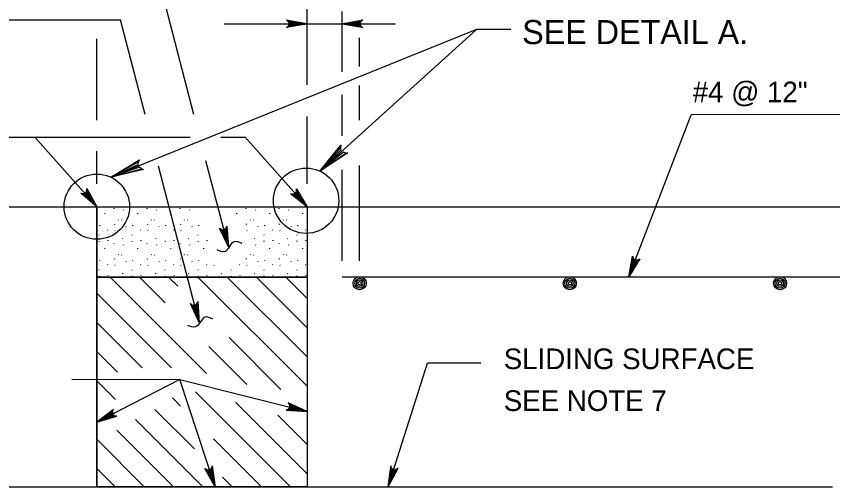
# Model space of a CAD drawing. Extents: x 2084213 to 2099800, y 976677 to 981262.
# Drawn here: x 2094864.1 to 2095252.4, y 979206.7 to 979430.6 of the extents above; entities that cross this region are included whole.
import ezdxf

# ---------------------------------------------------------------- set-up
doc = ezdxf.new("R2010")
doc.units = 0
for name, color, linetype in [('1', 7, 'Continuous'), ('2', 7, 'Continuous'), ('3', 7, 'Continuous')]:
    doc.layers.add(name, color=color, linetype=linetype)

msp = doc.modelspace()

# ---------------------------------------------------------------- linework, layer by layer
at = {"layer": '1'}
for p, q in [((2095002.37, 979398), (2095002.37, 979545.46)), ((2094948.57, 979383.86), (2094918.79, 979498.42)), ((2095019.04, 979404.17), (2095019.04, 979432.84)), ((2094732.6, 979428.91), (2094913.65, 979428.91)), ((2094925.34, 979383.93), (2094913.65, 979428.91)), ((2094962.99, 979427.06), (2095044.28, 979427.06)), ((2094902.37, 979381.16), (2094902.37, 979419.94)), ((2095027.37, 979406.69), (2095027.37, 979420.43)), ((2095027.37, 979381.14), (2095027.37, 979397.72)), ((2095019.04, 979373.78), (2095019.04, 979393.23)), ((2095155.38, 979306.66), (2095185.07, 979383.79)), ((2095259, 979383.92), (2095185.07, 979383.79)), ((2095002.37, 979350.87), (2095002.37, 979382.86)), ((2094794.55, 979373.09), (2094946.76, 979373.09)), ((2094902.37, 979339.99), (2094872.9, 979373.09)), ((2094961.33, 979373.09), (2094972.9, 979373.09)), ((2095002.37, 979339.99), (2094972.9, 979373.09)), ((2094902.37, 979350.87), (2094902.37, 979366.44)), ((2094964.96, 979320.8), (2094954.28, 979361.88)), ((2094951.1, 979284.85), (2094931.73, 979359.34)), ((2095019.04, 979314.25), (2095019.04, 979357.59)), ((2095027.37, 979314.25), (2095027.37, 979359.55)), ((2094435.37, 979339.99), (2094902.37, 979339.99)), ((2094902.37, 979339.99), (2095499.4, 979339.99)), ((2094902.37, 979339.99), (2094902.37, 979206.66)), ((2094906.14, 979336.57), (2094906.26, 979336.84)), ((2094910.47, 979339.26), (2094910.5, 979338.99)), ((2094915.1, 979338.47), (2094915.22, 979338.3)), ((2094921.84, 979336.57), (2094921.95, 979336.84)), ((2094926.16, 979339.26), (2094926.19, 979338.99)), ((2094930.79, 979338.47), (2094930.91, 979338.3)), ((2094937.53, 979336.57), (2094937.65, 979336.84)), ((2094941.86, 979339.26), (2094941.89, 979338.99)), ((2094946.48, 979338.47), (2094946.6, 979338.3)), ((2094968.91, 979336.57), (2094969.03, 979336.84)), ((2094973.24, 979339.26), (2094973.27, 979338.99)), ((2094977.87, 979338.47), (2094977.98, 979338.3)), ((2094984.61, 979336.57), (2094984.72, 979336.84)), ((2094988.93, 979339.26), (2094988.96, 979338.99)), ((2094993.56, 979338.47), (2094993.68, 979338.3)), ((2095000.3, 979336.57), (2095000.42, 979336.84)), ((2095002.37, 979339.99), (2095002.37, 979206.66)), ((2094912.49, 979333.76), (2094912.6, 979333.58)), ((2094914.17, 979333.69), (2094914.28, 979333.51)), ((2094928.18, 979333.76), (2094928.3, 979333.58)), ((2094929.86, 979333.69), (2094929.98, 979333.51)), ((2094943.87, 979333.76), (2094943.99, 979333.58)), ((2094945.55, 979333.69), (2094945.67, 979333.51)), ((2094975.26, 979333.76), (2094975.37, 979333.58)), ((2094976.94, 979333.69), (2094977.05, 979333.51)), ((2094990.95, 979333.76), (2094991.07, 979333.58)), ((2094992.63, 979333.69), (2094992.75, 979333.51)), ((2094903.75, 979330.89), (2094903.87, 979331.16)), ((2094907.44, 979329), (2094907.56, 979328.83)), ((2094910.75, 979331.57), (2094910.86, 979331.84)), ((2094910.93, 979328.68), (2094911.05, 979328.51)), ((2094916.14, 979330.55), (2094916.26, 979330.37)), ((2094919.45, 979330.89), (2094919.56, 979331.16)), ((2094923.13, 979329), (2094923.25, 979328.83)), ((2094926.44, 979331.57), (2094926.56, 979331.84)), ((2094926.62, 979328.68), (2094926.74, 979328.51)), ((2094931.84, 979330.55), (2094931.95, 979330.37)), ((2094935.14, 979330.89), (2094935.26, 979331.16)), ((2094938.83, 979329), (2094938.94, 979328.83)), ((2094942.13, 979331.57), (2094942.25, 979331.84)), ((2094942.31, 979328.68), (2094942.43, 979328.51)), ((2094947.53, 979330.55), (2094947.65, 979330.37)), ((2094950.83, 979330.89), (2094950.95, 979331.16)), ((2094973.51, 979331.57), (2094973.63, 979331.84)), ((2094973.7, 979328.68), (2094973.81, 979328.51)), ((2094978.91, 979330.55), (2094979.03, 979330.37)), ((2094982.22, 979330.89), (2094982.33, 979331.16)), ((2094985.9, 979329), (2094986.02, 979328.83)), ((2094989.21, 979331.57), (2094989.32, 979331.84)), ((2094989.39, 979328.68), (2094989.51, 979328.51)), ((2094994.61, 979330.55), (2094994.72, 979330.37)), ((2094997.91, 979330.89), (2094998.03, 979331.16)), ((2095001.6, 979329), (2095001.71, 979328.83)), ((2094903.36, 979326.59), (2094903.48, 979326.41)), ((2094914.67, 979324.61), (2094914.79, 979324.87)), ((2094919.05, 979326.59), (2094919.17, 979326.41)), ((2094930.36, 979324.61), (2094930.48, 979324.87)), ((2094946.05, 979324.61), (2094946.17, 979324.87)), ((2094950.44, 979326.59), (2094950.56, 979326.41)), ((2094977.44, 979324.61), (2094977.55, 979324.87)), ((2094981.82, 979326.59), (2094981.94, 979326.41)), ((2094993.13, 979324.61), (2094993.25, 979324.87)), ((2094997.52, 979326.59), (2094997.63, 979326.41)), ((2094903.46, 979323.4), (2094903.58, 979323.66)), ((2094907.55, 979323.97), (2094907.67, 979323.79)), ((2094910.47, 979322.66), (2094910.5, 979322.39)), ((2094915.1, 979321.88), (2094915.22, 979321.7)), ((2094919.15, 979323.4), (2094919.27, 979323.66)), ((2094923.24, 979323.97), (2094923.36, 979323.79)), ((2094926.16, 979322.66), (2094926.19, 979322.39)), ((2094930.79, 979321.88), (2094930.91, 979321.7)), ((2094934.84, 979323.4), (2094934.96, 979323.66)), ((2094938.94, 979323.97), (2094939.05, 979323.79)), ((2094941.86, 979322.66), (2094941.89, 979322.39)), ((2094946.48, 979321.88), (2094946.6, 979321.7)), ((2094950.54, 979323.4), (2094950.65, 979323.66)), ((2094954.63, 979323.97), (2094954.75, 979323.79)), ((2094977.87, 979321.88), (2094977.98, 979321.7)), ((2094981.92, 979323.4), (2094982.04, 979323.66)), ((2094986.01, 979323.97), (2094986.13, 979323.79)), ((2094988.93, 979322.66), (2094988.96, 979322.39)), ((2094993.56, 979321.88), (2094993.68, 979321.7)), ((2094997.61, 979323.4), (2094997.73, 979323.66)), ((2095001.71, 979323.97), (2095001.82, 979323.79)), ((2094906.14, 979319.98), (2094906.26, 979320.24)), ((2094912.49, 979317.16), (2094912.6, 979316.98)), ((2094914.17, 979317.09), (2094914.28, 979316.92)), ((2094921.84, 979319.98), (2094921.95, 979320.24)), ((2094928.18, 979317.16), (2094928.3, 979316.98)), ((2094929.86, 979317.09), (2094929.98, 979316.92)), ((2094937.53, 979319.98), (2094937.65, 979320.24)), ((2094943.87, 979317.16), (2094943.99, 979316.98)), ((2094945.55, 979317.09), (2094945.67, 979316.92)), ((2094953.22, 979319.98), (2094953.34, 979320.24)), ((2094975.26, 979317.16), (2094975.37, 979316.98)), ((2094976.94, 979317.09), (2094977.05, 979316.92)), ((2094984.61, 979319.98), (2094984.72, 979320.24)), ((2094990.95, 979317.16), (2094991.07, 979316.98)), ((2094992.63, 979317.09), (2094992.75, 979316.92)), ((2095000.3, 979319.98), (2095000.42, 979320.24)), ((2094903.75, 979314.29), (2094903.87, 979314.56)), ((2094910.75, 979314.97), (2094910.86, 979315.24)), ((2094916.14, 979313.95), (2094916.26, 979313.77)), ((2094919.45, 979314.29), (2094919.56, 979314.56)), ((2094926.44, 979314.97), (2094926.56, 979315.24)), ((2094931.84, 979313.95), (2094931.95, 979313.77)), ((2094935.14, 979314.29), (2094935.26, 979314.56)), ((2094942.13, 979314.97), (2094942.25, 979315.24)), ((2094947.53, 979313.95), (2094947.65, 979313.77)), ((2094950.83, 979314.29), (2094950.95, 979314.56)), ((2094973.51, 979314.97), (2094973.63, 979315.24)), ((2094978.91, 979313.95), (2094979.03, 979313.77)), ((2094982.22, 979314.29), (2094982.33, 979314.56)), ((2094989.21, 979314.97), (2094989.32, 979315.24)), ((2094994.61, 979313.95), (2094994.72, 979313.77)), ((2094997.91, 979314.29), (2094998.03, 979314.56)), ((2094903.36, 979309.99), (2094903.48, 979309.82)), ((2094907.44, 979312.41), (2094907.56, 979312.23)), ((2094910.93, 979312.09), (2094911.05, 979311.91)), ((2094919.05, 979309.99), (2094919.17, 979309.82)), ((2094923.13, 979312.41), (2094923.25, 979312.23)), ((2094926.62, 979312.09), (2094926.74, 979311.91)), ((2094934.75, 979309.99), (2094934.86, 979309.82)), ((2094938.83, 979312.41), (2094938.94, 979312.23)), ((2094942.31, 979312.09), (2094942.43, 979311.91)), ((2094950.44, 979309.99), (2094950.56, 979309.82)), ((2094954.52, 979312.41), (2094954.64, 979312.23)), ((2094958, 979312.09), (2094958.12, 979311.91)), ((2094966.13, 979309.99), (2094966.25, 979309.82)), ((2094970.21, 979312.41), (2094970.33, 979312.23)), ((2094973.7, 979312.09), (2094973.81, 979311.91)), ((2094981.82, 979309.99), (2094981.94, 979309.82)), ((2094985.9, 979312.41), (2094986.02, 979312.23)), ((2094989.39, 979312.09), (2094989.51, 979311.91)), ((2094997.52, 979309.99), (2094997.63, 979309.82)), ((2095001.6, 979312.41), (2095001.71, 979312.23)), ((2094902.37, 979306.44), (2095002.37, 979306.44)), ((2094903.46, 979306.8), (2094903.58, 979307.07)), ((2094907.55, 979307.37), (2094907.67, 979307.2)), ((2094954.58, 979260.54), (2094908.68, 979306.44)), ((2094914.67, 979308.01), (2094914.79, 979308.28)), ((2094919.15, 979306.8), (2094919.27, 979307.07)), ((2094934.8, 979294.25), (2094922.6, 979306.44)), ((2094923.24, 979307.37), (2094923.36, 979307.2)), ((2094930.36, 979308.01), (2094930.48, 979308.28)), ((2094934.84, 979306.8), (2094934.96, 979307.07)), ((2094940.91, 979302.06), (2094936.52, 979306.44)), ((2094938.94, 979307.37), (2094939.05, 979307.2)), ((2094946.05, 979308.01), (2094946.17, 979308.28)), ((2095002.37, 979254.51), (2094950.44, 979306.44)), ((2094950.54, 979306.8), (2094950.65, 979307.07)), ((2094954.63, 979307.37), (2094954.75, 979307.2)), ((2094961.74, 979308.01), (2094961.86, 979308.28)), ((2095002.37, 979268.43), (2094964.36, 979306.44)), ((2094966.23, 979306.8), (2094966.35, 979307.07)), ((2094970.32, 979307.37), (2094970.44, 979307.2)), ((2094977.44, 979308.01), (2094977.55, 979308.28)), ((2095002.37, 979282.35), (2094978.28, 979306.44)), ((2094981.92, 979306.8), (2094982.04, 979307.07)), ((2094986.01, 979307.37), (2094986.13, 979307.2)), ((2095002.37, 979296.27), (2094992.2, 979306.44)), ((2094993.13, 979308.01), (2094993.25, 979308.28)), ((2094997.61, 979306.8), (2094997.73, 979307.07)), ((2095001.71, 979307.37), (2095001.82, 979307.2)), ((2095019.04, 979306.66), (2095487.58, 979306.66)), ((2094937.96, 979263.24), (2094902.37, 979298.83)), ((2094923.97, 979263.31), (2094902.37, 979284.91)), ((2094989.97, 979252.99), (2094965.24, 979277.72)), ((2094912.22, 979261.14), (2094902.37, 979270.99)), ((2094973.73, 979255.31), (2094955.6, 979273.45)), ((2095040.9, 979206.66), (2095059.71, 979265.4)), ((2095085.01, 979265.4), (2095059.71, 979265.4)), ((2094890.53, 979257.78), (2094941.92, 979257.69)), ((2094941.92, 979257.69), (2094902.37, 979237.36)), ((2094911.25, 979248.19), (2094902.37, 979257.08)), ((2094958.59, 979206.66), (2094941.92, 979257.69)), ((2094941.92, 979257.69), (2095002.37, 979242.47)), ((2094994.55, 979206.66), (2094949.34, 979251.86)), ((2094942.21, 979245.07), (2094938.4, 979248.89)), ((2094948.75, 979224.62), (2094929.89, 979243.48)), ((2095002.37, 979212.75), (2094968.27, 979246.85)), ((2095002.37, 979226.67), (2094988.4, 979240.64)), ((2094952.79, 979206.66), (2094920.83, 979238.61)), ((2094938.87, 979206.66), (2094911.93, 979233.6)), ((2094924.95, 979206.66), (2094902.37, 979229.24)), ((2094980.63, 979206.66), (2094957.8, 979229.48)), ((2094911.03, 979206.66), (2094902.37, 979215.32)), ((2094966.71, 979206.66), (2094962.13, 979211.24)), ((2094435.37, 979206.66), (2094902.37, 979206.66)), ((2094652.37, 979206.66), (2095252.37, 979206.66))]:
    msp.add_line(p, q, dxfattribs=at)
for points in [[(2095002.37, 979427.06), (2094992.59, 979425.23), (2094992.96, 979425.49), (2094993.34, 979425.75), (2094993.53, 979426.08), (2094993.73, 979426.4), (2094993.78, 979426.73), (2094993.84, 979427.06), (2094993.78, 979427.39), (2094993.73, 979427.72), (2094993.53, 979428.04), (2094993.34, 979428.37), (2094992.96, 979428.63), (2094992.59, 979428.9), (2095002.37, 979427.06), (2094992.96, 979428.63), (2094993.34, 979428.37), (2095002.37, 979427.06), (2094993.53, 979428.04), (2094993.73, 979427.72), (2095002.37, 979427.06), (2094993.78, 979427.39), (2094993.84, 979427.06), (2095002.37, 979427.06), (2094993.78, 979426.73), (2094993.73, 979426.4), (2095002.37, 979427.06), (2094993.53, 979426.08), (2094993.34, 979425.75), (2095002.37, 979427.06), (2094992.96, 979425.49)], [(2095019.04, 979427.06), (2095028.83, 979428.9), (2095028.45, 979428.63), (2095028.07, 979428.37), (2095027.88, 979428.04), (2095027.68, 979427.72), (2095027.63, 979427.39), (2095027.57, 979427.06), (2095027.63, 979426.73), (2095027.68, 979426.4), (2095027.88, 979426.08), (2095028.07, 979425.75), (2095028.45, 979425.49), (2095028.83, 979425.23), (2095019.04, 979427.06), (2095028.45, 979425.49), (2095028.07, 979425.75), (2095019.04, 979427.06), (2095027.88, 979426.08), (2095027.68, 979426.4), (2095019.04, 979427.06), (2095027.63, 979426.73), (2095027.57, 979427.06), (2095019.04, 979427.06), (2095027.63, 979427.39), (2095027.68, 979427.72), (2095019.04, 979427.06), (2095027.88, 979428.04), (2095028.07, 979428.37), (2095019.04, 979427.06), (2095028.45, 979428.63)], [(2094902.37, 979339.99), (2094894.72, 979346.36), (2094895.16, 979346.23), (2094895.6, 979346.11), (2094895.98, 979346.17), (2094896.36, 979346.23), (2094896.65, 979346.39), (2094896.93, 979346.56), (2094897.15, 979346.81), (2094897.37, 979347.07), (2094897.5, 979347.42), (2094897.63, 979347.78), (2094897.59, 979348.24), (2094897.55, 979348.7), (2094902.37, 979339.99), (2094897.59, 979348.24), (2094897.63, 979347.78), (2094902.37, 979339.99), (2094897.5, 979347.42), (2094897.37, 979347.07), (2094902.37, 979339.99), (2094897.15, 979346.81), (2094896.93, 979346.56), (2094902.37, 979339.99), (2094896.65, 979346.39), (2094896.36, 979346.23), (2094902.37, 979339.99), (2094895.98, 979346.17), (2094895.6, 979346.11), (2094902.37, 979339.99), (2094895.16, 979346.23)], [(2095002.37, 979339.99), (2094994.53, 979346.13), (2094994.98, 979346.02), (2094995.42, 979345.91), (2094995.8, 979345.98), (2094996.17, 979346.05), (2094996.46, 979346.22), (2094996.74, 979346.4), (2094996.95, 979346.65), (2094997.16, 979346.91), (2094997.28, 979347.28), (2094997.39, 979347.64), (2094997.34, 979348.09), (2094997.29, 979348.55), (2095002.37, 979339.99), (2094997.34, 979348.09), (2094997.39, 979347.64), (2095002.37, 979339.99), (2094997.28, 979347.28), (2094997.16, 979346.91), (2095002.37, 979339.99), (2094996.95, 979346.65), (2094996.74, 979346.4), (2095002.37, 979339.99), (2094996.46, 979346.22), (2094996.17, 979346.05), (2095002.37, 979339.99), (2094995.8, 979345.98), (2094995.42, 979345.91), (2095002.37, 979339.99), (2094994.98, 979346.02)], [(2094964.96, 979320.8), (2094960.72, 979329.81), (2094961.07, 979329.51), (2094961.42, 979329.21), (2094961.78, 979329.1), (2094962.15, 979329), (2094962.48, 979329.03), (2094962.81, 979329.05), (2094963.12, 979329.19), (2094963.42, 979329.33), (2094963.69, 979329.6), (2094963.96, 979329.87), (2094964.12, 979330.3), (2094964.27, 979330.73), (2094964.96, 979320.8), (2094964.12, 979330.3), (2094963.96, 979329.87), (2094964.96, 979320.8), (2094963.69, 979329.6), (2094963.42, 979329.33), (2094964.96, 979320.8), (2094963.12, 979329.19), (2094962.81, 979329.05), (2094964.96, 979320.8), (2094962.48, 979329.03), (2094962.15, 979329), (2094964.96, 979320.8), (2094961.78, 979329.1), (2094961.42, 979329.21), (2094964.96, 979320.8), (2094961.07, 979329.51)], [(2095155.38, 979306.66), (2095157.19, 979316.45), (2095157.3, 979316), (2095157.4, 979315.56), (2095157.64, 979315.26), (2095157.88, 979314.96), (2095158.16, 979314.79), (2095158.45, 979314.62), (2095158.77, 979314.55), (2095159.1, 979314.49), (2095159.48, 979314.55), (2095159.85, 979314.62), (2095160.23, 979314.87), (2095160.61, 979315.13), (2095155.38, 979306.66), (2095160.23, 979314.87), (2095159.85, 979314.62), (2095155.38, 979306.66), (2095159.48, 979314.55), (2095159.1, 979314.49), (2095155.38, 979306.66), (2095158.77, 979314.55), (2095158.45, 979314.62), (2095155.38, 979306.66), (2095158.16, 979314.79), (2095157.88, 979314.96), (2095155.38, 979306.66), (2095157.64, 979315.26), (2095157.4, 979315.56), (2095155.38, 979306.66), (2095157.3, 979316)], [(2094951.1, 979284.85), (2094946.86, 979293.86), (2094947.21, 979293.56), (2094947.56, 979293.26), (2094947.92, 979293.15), (2094948.29, 979293.05), (2094948.62, 979293.08), (2094948.95, 979293.1), (2094949.26, 979293.24), (2094949.56, 979293.38), (2094949.83, 979293.65), (2094950.1, 979293.92), (2094950.25, 979294.35), (2094950.41, 979294.78), (2094951.1, 979284.85), (2094950.25, 979294.35), (2094950.1, 979293.92), (2094951.1, 979284.85), (2094949.83, 979293.65), (2094949.56, 979293.38), (2094951.1, 979284.85), (2094949.26, 979293.24), (2094948.95, 979293.1), (2094951.1, 979284.85), (2094948.62, 979293.08), (2094948.29, 979293.05), (2094951.1, 979284.85), (2094947.92, 979293.15), (2094947.56, 979293.26), (2094951.1, 979284.85), (2094947.21, 979293.56)], [(2094902.37, 979237.36), (2094911.91, 979240.21), (2094911.46, 979240.27), (2094911, 979240.33), (2094910.68, 979240.53), (2094910.36, 979240.73), (2094910.16, 979241), (2094909.96, 979241.26), (2094909.86, 979241.58), (2094909.76, 979241.9), (2094909.78, 979242.28), (2094909.8, 979242.66), (2094910.02, 979243.06), (2094910.24, 979243.47), (2094902.37, 979237.36), (2094910.02, 979243.06), (2094909.8, 979242.66), (2094902.37, 979237.36), (2094909.78, 979242.28), (2094909.76, 979241.9), (2094902.37, 979237.36), (2094909.86, 979241.58), (2094909.96, 979241.26), (2094902.37, 979237.36), (2094910.16, 979241), (2094910.36, 979240.73), (2094902.37, 979237.36), (2094910.68, 979240.53), (2094911, 979240.33), (2094902.37, 979237.36), (2094911.46, 979240.27)], [(2095002.37, 979242.47), (2094993.33, 979246.64), (2094993.63, 979246.29), (2094993.93, 979245.95), (2094994.04, 979245.58), (2094994.15, 979245.21), (2094994.12, 979244.88), (2094994.1, 979244.55), (2094993.96, 979244.25), (2094993.83, 979243.94), (2094993.56, 979243.67), (2094993.29, 979243.4), (2094992.86, 979243.24), (2094992.43, 979243.08), (2095002.37, 979242.47), (2094992.86, 979243.24), (2094993.29, 979243.4), (2095002.37, 979242.47), (2094993.56, 979243.67), (2094993.83, 979243.94), (2095002.37, 979242.47), (2094993.96, 979244.25), (2094994.1, 979244.55), (2095002.37, 979242.47), (2094994.12, 979244.88), (2094994.15, 979245.21), (2095002.37, 979242.47), (2094994.04, 979245.58), (2094993.93, 979245.95), (2095002.37, 979242.47), (2094993.63, 979246.29)], [(2094958.59, 979206.66), (2094953.81, 979215.39), (2094954.17, 979215.11), (2094954.54, 979214.84), (2094954.91, 979214.75), (2094955.28, 979214.67), (2094955.61, 979214.72), (2094955.94, 979214.77), (2094956.23, 979214.92), (2094956.53, 979215.08), (2094956.78, 979215.36), (2094957.03, 979215.65), (2094957.16, 979216.09), (2094957.29, 979216.53), (2094958.59, 979206.66), (2094957.16, 979216.09), (2094957.03, 979215.65), (2094958.59, 979206.66), (2094956.78, 979215.36), (2094956.53, 979215.08), (2094958.59, 979206.66), (2094956.23, 979214.92), (2094955.94, 979214.77), (2094958.59, 979206.66), (2094955.61, 979214.72), (2094955.28, 979214.67), (2094958.59, 979206.66), (2094954.91, 979214.75), (2094954.54, 979214.84), (2094958.59, 979206.66), (2094954.17, 979215.11)], [(2095040.9, 979206.66), (2095045.63, 979215.42), (2095045.27, 979215.14), (2095044.9, 979214.86), (2095044.53, 979214.77), (2095044.16, 979214.69), (2095043.83, 979214.74), (2095043.5, 979214.78), (2095043.21, 979214.94), (2095042.91, 979215.09), (2095042.66, 979215.37), (2095042.4, 979215.66), (2095042.27, 979216.1), (2095042.14, 979216.54), (2095040.9, 979206.66), (2095042.27, 979216.1), (2095042.4, 979215.66), (2095040.9, 979206.66), (2095042.66, 979215.37), (2095042.91, 979215.09), (2095040.9, 979206.66), (2095043.21, 979214.94), (2095043.5, 979214.78), (2095040.9, 979206.66), (2095043.83, 979214.74), (2095044.16, 979214.69), (2095040.9, 979206.66), (2095044.53, 979214.77), (2095044.9, 979214.86), (2095040.9, 979206.66), (2095045.27, 979215.14)]]:
    msp.add_lwpolyline(points, dxfattribs=at)
for points in [[(2094902.37, 979339.99), (2095002.37, 979339.99), (2095002.37, 979306.44), (2094902.37, 979306.44)], [(2094902.37, 979306.44), (2095002.37, 979306.44), (2095002.37, 979206.66), (2094902.37, 979206.66)]]:
    msp.add_lwpolyline(points, close=True, dxfattribs=at)
for centre, radius in [((2095027.37, 979303.54), 3.12), ((2095027.37, 979303.54), 2.34), ((2095127.37, 979303.54), 3.12), ((2095127.37, 979303.54), 2.34), ((2095227.37, 979303.54), 3.12), ((2095227.37, 979303.54), 2.34), ((2095027.37, 979303.54), 1.56), ((2095027.37, 979303.54), 0.781), ((2095127.37, 979303.54), 1.56), ((2095127.37, 979303.54), 0.781), ((2095227.37, 979303.54), 1.56), ((2095227.37, 979303.54), 0.781)]:
    msp.add_circle(centre, radius, dxfattribs=at)
for points in [[(2094971.42, 979322.42), (2094967.67, 979323.32), (2094963.2, 979318.65), (2094959.54, 979319.38)], [(2094957.56, 979286.47), (2094953.81, 979287.37), (2094949.33, 979282.7), (2094945.68, 979283.43)]]:
    msp.add_spline(points, degree=3, dxfattribs=at)
at = {"layer": '2'}
msp.add_line((2095082.97, 979424.37), (2094909.06, 979354.03), dxfattribs=at)
for points in [[(2095099.37, 979424.37), (2095082.97, 979424.37), (2095008.49, 979356.94)], [(2095020.78, 979365.54), (2095019.65, 979365.97), (2095008.49, 979356.94), (2095020.78, 979365.54), (2095021.79, 979365.57), (2095008.49, 979356.94), (2095018.64, 979367.08), (2095018.31, 979368.22), (2095008.49, 979356.94), (2095018.43, 979369.29), (2095018.31, 979368.22)], [(2094923.54, 979357.95), (2094922.62, 979358.74), (2094909.06, 979354.03), (2094923.54, 979357.95), (2094924.49, 979357.63), (2094909.06, 979354.03), (2094922.04, 979360.12), (2094922.12, 979361.3), (2094909.06, 979354.03), (2094922.6, 979362.27), (2094922.12, 979361.3)]]:
    msp.add_lwpolyline(points, dxfattribs=at)
for centre in [(2095001.92, 979342.84), (2094902.37, 979339.99)]:
    msp.add_circle(centre, 15.55, dxfattribs=at)

# ---------------------------------------------------------------- texts
at = {"layer": '1'}
for s, height, p in [('#4 @ 12"', 9.843, (2095185.83, 979389.7)), ('SLIDING SURFACE', 9.8425, (2095095.92, 979262.63)), ('SEE NOTE 7', 9.843, (2095095.92, 979242.71))]:
    msp.add_text(s, height=height, dxfattribs=at).set_placement(p)
at = {"layer": '3'}
msp.add_text('SEE DETAIL A.', height=11.478, dxfattribs=at).set_placement((2095104.7, 979417.38))

doc.saveas('drawing.dxf')
